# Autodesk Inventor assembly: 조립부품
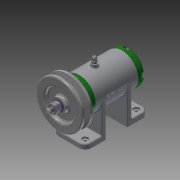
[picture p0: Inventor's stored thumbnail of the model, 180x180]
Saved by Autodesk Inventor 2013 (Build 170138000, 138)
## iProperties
Created: 2017-02
Part Number: 조립부품
Document SubType Name: Assembly
Designer: Administrator
Author: Administrator
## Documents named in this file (16)
- C:\Users\Administrator\Desktop\470208V1002\조립부품.iam
- C:\Users\Administrator\Desktop\470208V1002\본체.ipt
- C:\Users\Administrator\Desktop\470208V1002\V벨트풀리.ipt
- C:\Users\Administrator\Desktop\470208V1002\너트 M 8.ipt
- C:\Users\Administrator\Desktop\470208V1002\니플 M 6 x 0.75.ipt
- C:\Users\Administrator\Desktop\470208V1002\뒤커버.ipt
- C:\Users\Administrator\Desktop\470208V1002\베어링 15 x 32 x 9.ipt
- C:\Users\Administrator\Desktop\470208V1002\볼트 M 6 x 8.ipt
- C:\Users\Administrator\Desktop\470208V1002\볼트 M4 x 12.ipt
- C:\Users\Administrator\Desktop\470208V1002\스프링와셔 8.ipt
- C:\Users\Administrator\Desktop\470208V1002\앞커버.ipt
- C:\Users\Administrator\Desktop\470208V1002\오일 실 15 25 7.ipt
- C:\Users\Administrator\Desktop\470208V1002\와셔 6x11.5.ipt
- C:\Users\Administrator\Desktop\470208V1002\와셔 8x17.ipt
- C:\Users\Administrator\Desktop\470208V1002\축.ipt
- C:\Users\Administrator\Desktop\470208V1002\키 3 x 3 x 12.ipt
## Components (11 placed, 3 different names)
1. V벨트풀리:1
2. KS B 2023 6002 - 15 x 32 x 9:1
3. KS B 2023 6002 - 15 x 32 x 9:2
4. ISO 4762 M4 x 12:1
5. ISO 4762 M4 x 12:3
6. ISO 4762 M4 x 12:4
7. ISO 4762 M4 x 12:5
8. ISO 4762 M4 x 12:2
9. ISO 4762 M4 x 12:6
10. ISO 4762 M4 x 12:7
11. ISO 4762 M4 x 12:8
